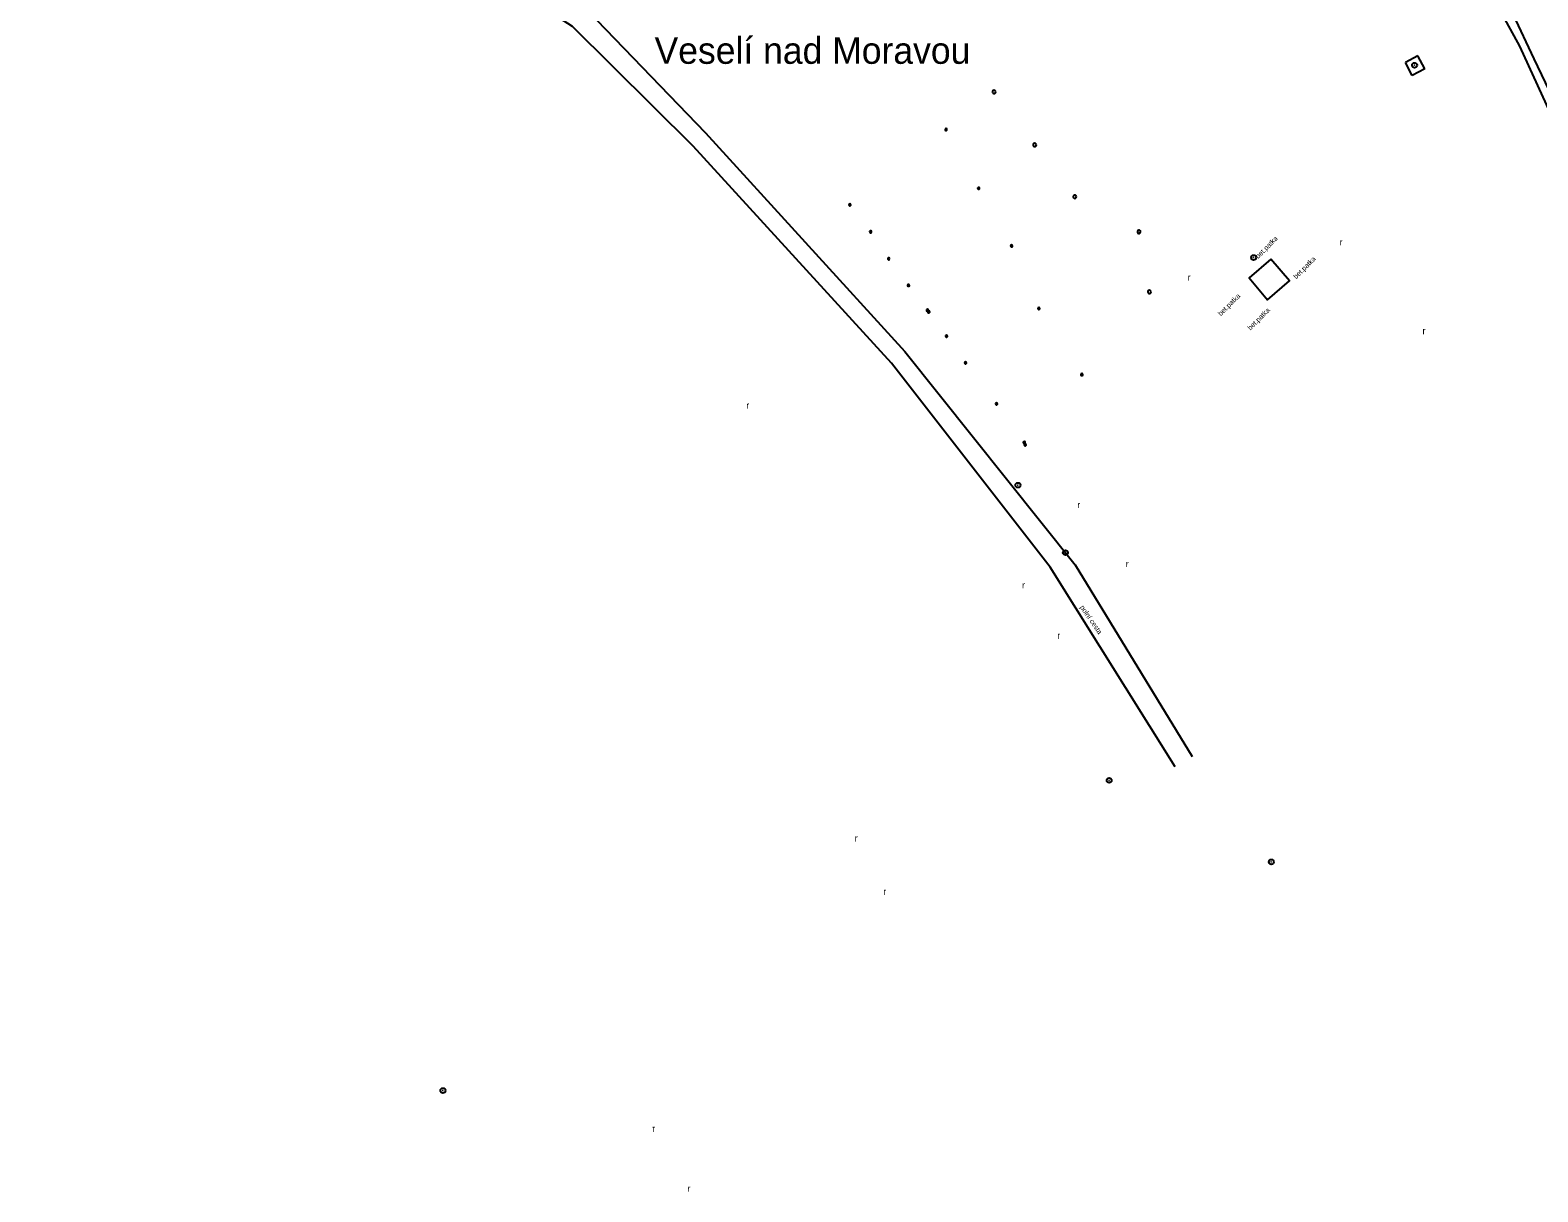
# Model space of a CAD drawing. Extents: x -545714 to -543531, y -1196215 to -1194297.
# Drawn here: x -545381.7 to -545154.6, y -1195089 to -1194914.1 of the extents above; entities that cross this region are included whole.
import ezdxf

# ---------------------------------------------------------------- set-up
doc = ezdxf.new("R2010")
doc.units = 0
for name, color, linetype in [('MAP_ZN_BP', 7, 'Continuous'), ('NÁZVY_SÍDEL_JEDNOTKY', 7, 'Continuous'), ('POMOC_POPIS', 7, 'Continuous'), ('ROZHRANÍ_PLOCH', 7, 'Continuous'), ('ZELEŇ', 7, 'Continuous'), ('ZN_DOPLŇKOVÉ', 7, 'Continuous'), ('ZN_KULTUR', 7, 'Continuous')]:
    doc.layers.add(name, color=color, linetype=linetype)

msp = doc.modelspace()

# ---------------------------------------------------------------- linework, layer by layer
at = {"layer": 'MAP_ZN_BP'}
for centre, radius in [((-545173.13, -1194919.36), 0.375), ((-545173.13, -1194919.36), 0.0005), ((-545197.37, -1194948.31), 0.375), ((-545197.37, -1194948.31), 0.0005), ((-545232.87, -1194982.57), 0.375), ((-545232.87, -1194982.57), 0.0005), ((-545225.71, -1194992.73), 0.375), ((-545225.71, -1194992.73), 0.0005), ((-545219.13, -1195027.01), 0.375), ((-545219.13, -1195027.01), 0.0005), ((-545194.71, -1195039.28), 0.375), ((-545194.71, -1195039.28), 0.0005), ((-545319.48, -1195073.71), 0.375), ((-545319.48, -1195073.71), 0.0005)]:
    msp.add_circle(centre, radius, dxfattribs=at)
at = {"layer": 'ROZHRANÍ_PLOCH'}
for points in [[(-545380.79, -1194882.48), (-545337.18, -1194894.38), (-545309.11, -1194903.97), (-545297.73, -1194911.09), (-545279.92, -1194929.52), (-545249.93, -1194962.44), (-545224.27, -1194994.57), (-545206.61, -1195023.4)], [(-545209.2, -1195024.96), (-545228.02, -1194994.94), (-545251.9, -1194964.18), (-545281.8, -1194931.52), (-545299.99, -1194913.53), (-545310.3, -1194906.86), (-545338.49, -1194897.83), (-545381.66, -1194886.33)]]:
    msp.add_lwpolyline(points, dxfattribs=at)
at = {"layer": 'ZELEŇ'}
msp.add_lwpolyline([(-545163.73, -1194904.73), (-545157.33, -1194916.5), (-545145.95, -1194941.38), (-545132.25, -1194968.89), (-545113.82, -1195007.18), (-545098.92, -1195038.71), (-545087.42, -1195063.39), (-545077.4, -1195058.61), (-545059.16, -1195048.98)], dxfattribs=at)
at = {"layer": 'ZN_DOPLŇKOVÉ'}
for points in [[(-545161.48, -1194904.87), (-545155.15, -1194918.38), (-545140.91, -1194948.15)], [(-545172.62, -1194917.95), (-545174.51, -1194918.92)], [(-545171.6, -1194919.92), (-545172.62, -1194917.95)], [(-545173.49, -1194920.89), (-545174.51, -1194918.92)], [(-545171.6, -1194919.92), (-545173.49, -1194920.89)], [(-545236.19, -1194923.37), (-545236.23, -1194923.24), (-545236.34, -1194923.14), (-545236.47, -1194923.12), (-545236.6, -1194923.18), (-545236.68, -1194923.3), (-545236.68, -1194923.44), (-545236.61, -1194923.56), (-545236.48, -1194923.62), (-545236.34, -1194923.6), (-545236.24, -1194923.51), (-545236.19, -1194923.37)], [(-545243.55, -1194929.05), (-545243.59, -1194928.95), (-545243.69, -1194928.9), (-545243.79, -1194928.93), (-545243.85, -1194929.02), (-545243.83, -1194929.13), (-545243.75, -1194929.19), (-545243.64, -1194929.19), (-545243.56, -1194929.11), (-545243.55, -1194929.05)], [(-545230.09, -1194931.35), (-545230.13, -1194931.22), (-545230.24, -1194931.12), (-545230.37, -1194931.1), (-545230.5, -1194931.16), (-545230.58, -1194931.28), (-545230.58, -1194931.42), (-545230.51, -1194931.54), (-545230.38, -1194931.6), (-545230.24, -1194931.58), (-545230.14, -1194931.49), (-545230.09, -1194931.35)], [(-545238.64, -1194937.89), (-545238.68, -1194937.79), (-545238.78, -1194937.74), (-545238.88, -1194937.77), (-545238.94, -1194937.86), (-545238.92, -1194937.97), (-545238.84, -1194938.03), (-545238.73, -1194938.03), (-545238.65, -1194937.95), (-545238.64, -1194937.89)], [(-545258.03, -1194940.38), (-545258.07, -1194940.28), (-545258.17, -1194940.23), (-545258.27, -1194940.26), (-545258.33, -1194940.35), (-545258.31, -1194940.46), (-545258.23, -1194940.52), (-545258.12, -1194940.52), (-545258.04, -1194940.44), (-545258.03, -1194940.38)], [(-545224.06, -1194939.15), (-545224.1, -1194939.02), (-545224.21, -1194938.92), (-545224.34, -1194938.9), (-545224.47, -1194938.96), (-545224.55, -1194939.08), (-545224.55, -1194939.22), (-545224.48, -1194939.34), (-545224.35, -1194939.4), (-545224.21, -1194939.38), (-545224.11, -1194939.29), (-545224.06, -1194939.15)], [(-545254.91, -1194944.42), (-545254.95, -1194944.32), (-545255.05, -1194944.27), (-545255.15, -1194944.3), (-545255.21, -1194944.39), (-545255.19, -1194944.5), (-545255.11, -1194944.56), (-545255, -1194944.56), (-545254.92, -1194944.48), (-545254.91, -1194944.42)], [(-545214.39, -1194944.43), (-545214.43, -1194944.3), (-545214.54, -1194944.2), (-545214.67, -1194944.18), (-545214.8, -1194944.24), (-545214.88, -1194944.36), (-545214.88, -1194944.5), (-545214.81, -1194944.62), (-545214.68, -1194944.68), (-545214.54, -1194944.66), (-545214.44, -1194944.57), (-545214.39, -1194944.43)], [(-545233.68, -1194946.56), (-545233.72, -1194946.46), (-545233.82, -1194946.41), (-545233.92, -1194946.44), (-545233.98, -1194946.53), (-545233.96, -1194946.64), (-545233.88, -1194946.7), (-545233.77, -1194946.7), (-545233.69, -1194946.62), (-545233.68, -1194946.56)], [(-545252.19, -1194948.49), (-545252.23, -1194948.39), (-545252.33, -1194948.34), (-545252.43, -1194948.37), (-545252.49, -1194948.46), (-545252.47, -1194948.57), (-545252.39, -1194948.63), (-545252.28, -1194948.63), (-545252.2, -1194948.55), (-545252.19, -1194948.49)], [(-545194.79, -1194948.57), (-545198.06, -1194951.37), (-545195.27, -1194954.65), (-545191.98, -1194951.83), (-545194.79, -1194948.57)], [(-545249.21, -1194952.49), (-545249.25, -1194952.39), (-545249.35, -1194952.34), (-545249.45, -1194952.37), (-545249.51, -1194952.46), (-545249.49, -1194952.57), (-545249.41, -1194952.63), (-545249.3, -1194952.63), (-545249.22, -1194952.55), (-545249.21, -1194952.49)], [(-545212.8, -1194953.48), (-545212.84, -1194953.35), (-545212.95, -1194953.25), (-545213.08, -1194953.23), (-545213.21, -1194953.29), (-545213.29, -1194953.41), (-545213.29, -1194953.55), (-545213.22, -1194953.67), (-545213.09, -1194953.73), (-545212.95, -1194953.71), (-545212.85, -1194953.62), (-545212.8, -1194953.48)], [(-545246.37, -1194956.23), (-545246.41, -1194956.13), (-545246.51, -1194956.08), (-545246.61, -1194956.11), (-545246.67, -1194956.2), (-545246.65, -1194956.31), (-545246.57, -1194956.36), (-545246.45, -1194956.35), (-545246.4, -1194956.3), (-545246.37, -1194956.23)], [(-545246.15, -1194956.48), (-545246.19, -1194956.38), (-545246.29, -1194956.33), (-545246.39, -1194956.37), (-545246.45, -1194956.45), (-545246.43, -1194956.56), (-545246.35, -1194956.62), (-545246.24, -1194956.62), (-545246.16, -1194956.54), (-545246.15, -1194956.48)], [(-545229.57, -1194955.99), (-545229.61, -1194955.89), (-545229.71, -1194955.84), (-545229.81, -1194955.87), (-545229.87, -1194955.96), (-545229.85, -1194956.07), (-545229.77, -1194956.13), (-545229.66, -1194956.13), (-545229.58, -1194956.05), (-545229.57, -1194955.99)], [(-545243.47, -1194960.14), (-545243.51, -1194960.04), (-545243.61, -1194959.99), (-545243.71, -1194960.02), (-545243.77, -1194960.11), (-545243.75, -1194960.22), (-545243.67, -1194960.28), (-545243.56, -1194960.28), (-545243.48, -1194960.2), (-545243.47, -1194960.14)], [(-545240.61, -1194964.17), (-545240.65, -1194964.07), (-545240.75, -1194964.02), (-545240.85, -1194964.05), (-545240.91, -1194964.14), (-545240.89, -1194964.25), (-545240.81, -1194964.31), (-545240.7, -1194964.31), (-545240.62, -1194964.23), (-545240.61, -1194964.17)], [(-545223.11, -1194965.93), (-545223.15, -1194965.83), (-545223.25, -1194965.78), (-545223.35, -1194965.81), (-545223.41, -1194965.9), (-545223.39, -1194966.01), (-545223.31, -1194966.07), (-545223.2, -1194966.07), (-545223.12, -1194965.99), (-545223.11, -1194965.93)], [(-545235.94, -1194970.33), (-545235.98, -1194970.23), (-545236.08, -1194970.18), (-545236.18, -1194970.21), (-545236.24, -1194970.3), (-545236.22, -1194970.41), (-545236.14, -1194970.47), (-545236.03, -1194970.47), (-545235.95, -1194970.39), (-545235.94, -1194970.33)], [(-545231.76, -1194976.15), (-545231.8, -1194976.05), (-545231.9, -1194976), (-545232, -1194976.03), (-545232.06, -1194976.12), (-545232.04, -1194976.23), (-545231.96, -1194976.29), (-545231.85, -1194976.29), (-545231.77, -1194976.21), (-545231.76, -1194976.15)], [(-545231.62, -1194976.5), (-545231.66, -1194976.4), (-545231.76, -1194976.35), (-545231.86, -1194976.38), (-545231.92, -1194976.47), (-545231.9, -1194976.58), (-545231.82, -1194976.64), (-545231.71, -1194976.64), (-545231.63, -1194976.56), (-545231.62, -1194976.5)]]:
    msp.add_lwpolyline(points, dxfattribs=at)

# ---------------------------------------------------------------- texts
at = {"layer": 'NÁZVY_SÍDEL_JEDNOTKY'}
msp.add_text('Veselí nad Moravou', height=4, dxfattribs=at).set_placement((-545287.61, -1194919.14))
at = {"layer": 'POMOC_POPIS'}
for s, rotation, p in [('bet.patka', 45, (-545196.67, -1194948.53)), ('bet.patka', 45, (-545190.96, -1194951.6)), ('bet.patka', 45, (-545202.31, -1194957.17)), ('bet.patka', 45, (-545197.86, -1194959.31)), ('polní cesta', 304.38, (-545223.57, -1195000.96))]:
    msp.add_text(s, height=0.75, rotation=rotation, dxfattribs=at).set_placement(p)
at = {"layer": 'ZN_KULTUR'}
for p in [(-545184.41, -1194946.48), (-545207.32, -1194951.78), (-545171.93, -1194959.85), (-545273.79, -1194971.05), (-545223.93, -1194986.03), (-545216.63, -1194994.91), (-545232.25, -1194998.11), (-545226.95, -1195005.71), (-545257.46, -1195036.22), (-545253.16, -1195044.25), (-545287.96, -1195079.93), (-545282.66, -1195088.95)]:
    msp.add_text('r', height=1, dxfattribs=at).set_placement(p)

doc.saveas('drawing.dxf')
